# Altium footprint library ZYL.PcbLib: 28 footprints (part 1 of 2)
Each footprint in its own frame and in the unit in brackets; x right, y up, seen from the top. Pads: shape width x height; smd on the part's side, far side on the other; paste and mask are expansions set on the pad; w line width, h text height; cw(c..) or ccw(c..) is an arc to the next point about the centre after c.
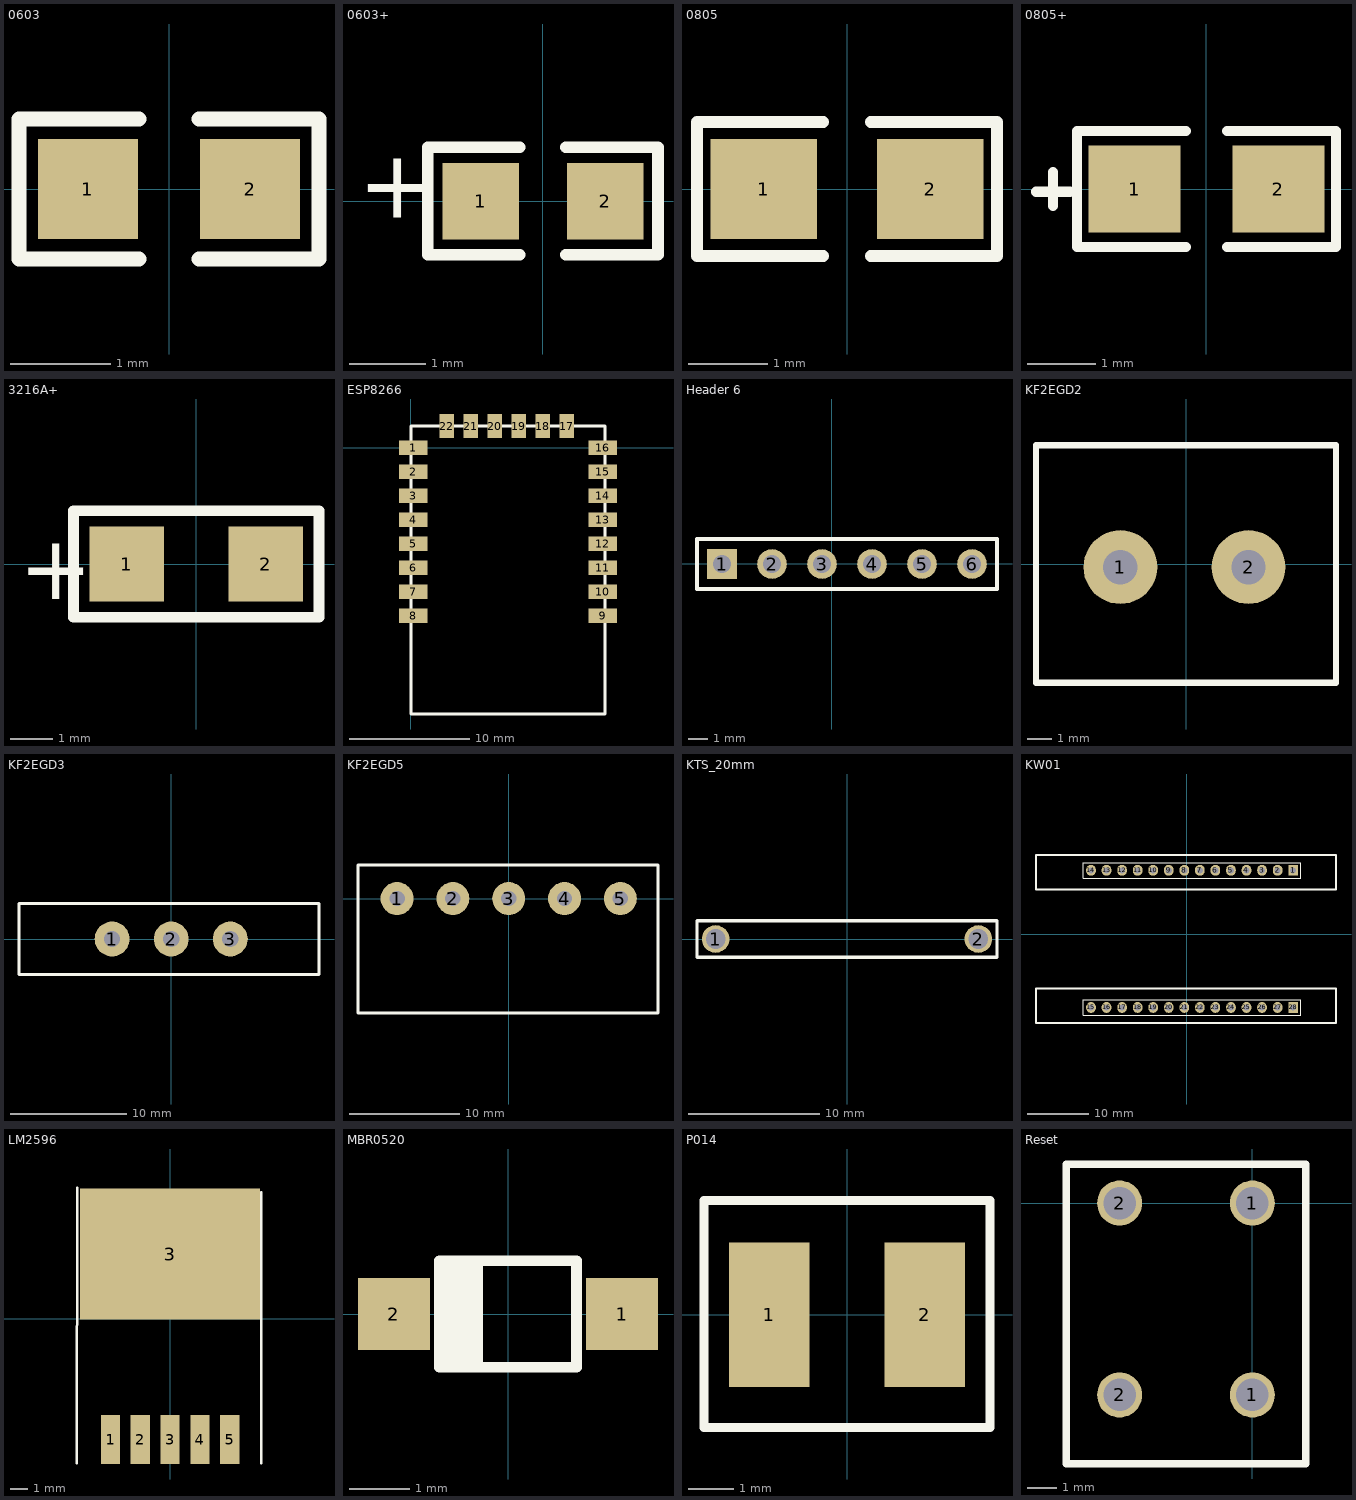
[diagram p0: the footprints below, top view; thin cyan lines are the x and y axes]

## 0603 [mm]
pads (2):
  rect 1x1 smd: 1(-0.81,0) 2(0.81,0)
Top Overlay:
  lines w0.15: -0.3,-0.7 -1.5,-0.7 -1.5,0.7 -0.3,0.7 ; 0.3,-0.7 1.5,-0.7 1.5,0.7 0.3,0.7

## 0603+ [mm]
pads (2):
  rect 1x1 smd: 1(-0.81,0) 2(0.81,0)
Top Overlay:
  lines w0.15: -0.3,-0.7 -1.5,-0.7 -1.5,0.7 -0.3,0.7 ; 0.3,-0.7 1.5,-0.7 1.5,0.7 0.3,0.7
  text "+" at -2.413,-0.508 h1.52

## 0805 [mm]
pads (2):
  rect 1.35x1.27 smd: 1(-1.055,0) 2(1.055,0)
Top Overlay:
  lines w0.15: -0.3,-0.85 -1.9,-0.85 -1.9,0.85 -0.3,0.85 ; 0.3,-0.85 1.9,-0.85 1.9,0.85 0.3,0.85

## 0805+ [mm]
pads (2):
  rect 1.35x1.27 smd: 1(-1.055,0) 2(1.055,0)
Top Overlay:
  lines w0.15: -2.5,-0.039 -2,-0.039 ; -2.25,-0.25 -2.25,0.25 ; -0.3,-0.85 -1.9,-0.85 -1.9,0.85 -0.3,0.85 ; 0.3,-0.85 1.9,-0.85 1.9,0.85 0.3,0.85

## 3216A+ [mil]
pads (2):
  rect 70x70 smd: 1(-65,0) 2(65,0)
Top Overlay:
  lines w10: -115,-50 -115,40 -115,50 115,50 115,-50 -115,-50
  text "+" at -166,-33 h60

## ESP8266 [mm]
pads (22):
  rect 2.4x1.2 smd: 1(0.2,0) 2(0.2,-2) 3(0.2,-4) 4(0.2,-6) 5(0.2,-8) 6(0.2,-10) 7(0.2,-12) 8(0.2,-14) 9(16,-14) 10(16,-12) 11(16,-10) 12(16,-8) 13(16,-6) 14(16,-4) 15(16,-2) 16(16,0)
  rect 1.2x2 smd: 17(13,1.8) 18(11,1.8) 19(9,1.8) 20(7,1.8) 21(5,1.8) 22(3,1.8)
Top Overlay:
  lines w0.254: 0,-22.2 0,1.8 16.2,1.8 16.2,-22.2 0,-22.2

## Header 6 [mm]
pads (6):
  rect 1.5x1.5 hole 0.9: 1(-5.588,0)
  round 1.5 hole 0.9: 2(-3.048,0) 3(-0.508,0) 4(2.032,0) 5(4.572,0) 6(7.112,0)
Top Overlay:
  lines w0.2: -6.858,-1.27 8.382,-1.27 8.382,1.27 -6.858,1.27 -6.858,-1.27

## KF2EGD2 [mm]
pads (2):
  round 3 hole 1.4: 1(-2.667,-0.127) 2(2.54,-0.127)
Top Overlay:
  lines w0.254: -6.096,-4.826 -6.096,4.826 6.096,4.826 6.096,-4.826 -6.096,-4.826

## KF2EGD3 [mm]
pads (3):
  round 3 hole 1.4: 1(-5.08,0) 2(0,0) 3(5.08,0)
Top Overlay:
  lines w0.254: -13.081,-3.048 12.7,-3.048 12.7,3.048 -13.081,3.048 -13.081,-3.048

## KF2EGD5 [mm]
pads (5):
  round 3 hole 1.4: 1(-10.16,0) 2(-5.08,0) 3(0,0) 4(5.08,0) 5(10.16,0)
Top Overlay:
  lines w0.254: -13.716,-10.414 -13.716,3.048 13.589,3.048 13.589,-10.414 -13.716,-10.414

## KTS_20mm [mm]
pads (2):
  round 2.1 hole 1.5: 1(-10.008,0) 2(10.008,0)
Top Overlay:
  lines w0.254: -11.43,-1.397 -11.43,1.397 11.43,1.397 11.43,-1.397 -11.43,-1.397

## KW01 [mil]
pads (28):
  rect 62x70 hole 39: 1(685,410) 28(685,-472)
  oval 62x70 hole 39: 2(585,410) 3(485,410) 4(385,410) 5(285,410) 6(185,410) 7(85,410) 8(-15,410) 9(-115,410) 10(-215,410) 11(-315,410) 12(-415,410) 13(-515,410) 14(-615,410) 15(-615,-472) 16(-515,-472) 17(-415,-472) 18(-315,-472) 19(-215,-472) 20(-115,-472) 21(-15,-472) 22(85,-472) 23(185,-472) 24(285,-472) 25(385,-472) 26(485,-472) 27(585,-472)
Top Overlay:
  lines w7.87: -665,458 -665,360 735,360 735,458 ; -665,460 660,460 735,460 ; -665,-522 -665,-422 660,-422 735,-422 735,-522 -665,-522
  lines w10: -968.54,-572 -968.54,-350 960.59,-350 960.59,-572 -968.54,-572 ; -968.54,286.36 960.59,286.36 960.59,508.36 -968.54,508.36 -968.54,286.36

## LM2596 [mm] "D-PAK/TO-252-AA; 3 Leads (1 Cropped); Body 10.1 (inc. leads) x 6.6 mm (LxW max)"
height 2.4
pads (6):
  rect 1.1x2.8 smd: 1(-3.404,-6.9) 2(-1.702,-6.9) 3(0,-6.9) 4(1.702,-6.9) 5(3.404,-6.9)
  rect 10.3x7.5 smd: 3(0,3.7)
Top Overlay:
  lines w0.15: -5.334,-8.255 -5.3,7.5 ; 5.207,-8.255 5.207,7.245

## MBR0520 [mm]
pads (2):
  rect 1.2x1.2 smd: 1(1.905,0) 2(-1.905,0)
Top Overlay:
  rectangle: -1.143,-0.889 -0.508,0.889
  lines w0.178: -0.508,-0.889 -0.508,0.889 ; -1.143,-0.889 -1.143,0.889 1.143,0.889 1.143,0.445 1.143,-0.445 1.143,-0.889 -1.143,-0.889

## P014 [mm]
pads (2):
  rect 1.78x3.2 smd: 1(-1.725,0) 2(1.725,0)
Top Overlay:
  lines w0.2: -3.175,0 -3.175,-2.5 3.175,-2.5 ; -3.175,0.04 -3.175,2.54 3.175,2.54 3.175,-2.46

## Reset [mil]
pads (4):
  round 60 hole 43.31: 1(0,-255.91) 1(0,0) 2(-177.17,-255.91) 2(-177.17,0)
Top Overlay:
  lines w10: -248.58,-347.95 -248.58,52.05 71.42,52.05 71.42,-327.95 71.42,-347.95 -248.58,-347.95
